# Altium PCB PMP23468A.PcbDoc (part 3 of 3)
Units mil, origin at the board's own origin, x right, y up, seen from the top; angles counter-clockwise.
Board outline 5250 x 3500 mil, 6 copper layers (Top Layer, Signal Layer 1, Signal Layer 2, Signal Layer 3, Signal Layer 4, Bottom Layer), stack 61.8 mil thick; 157 components, 73 nets, 403 pads, 842 vias.
Unrouted connection lines stored in the file: 3.
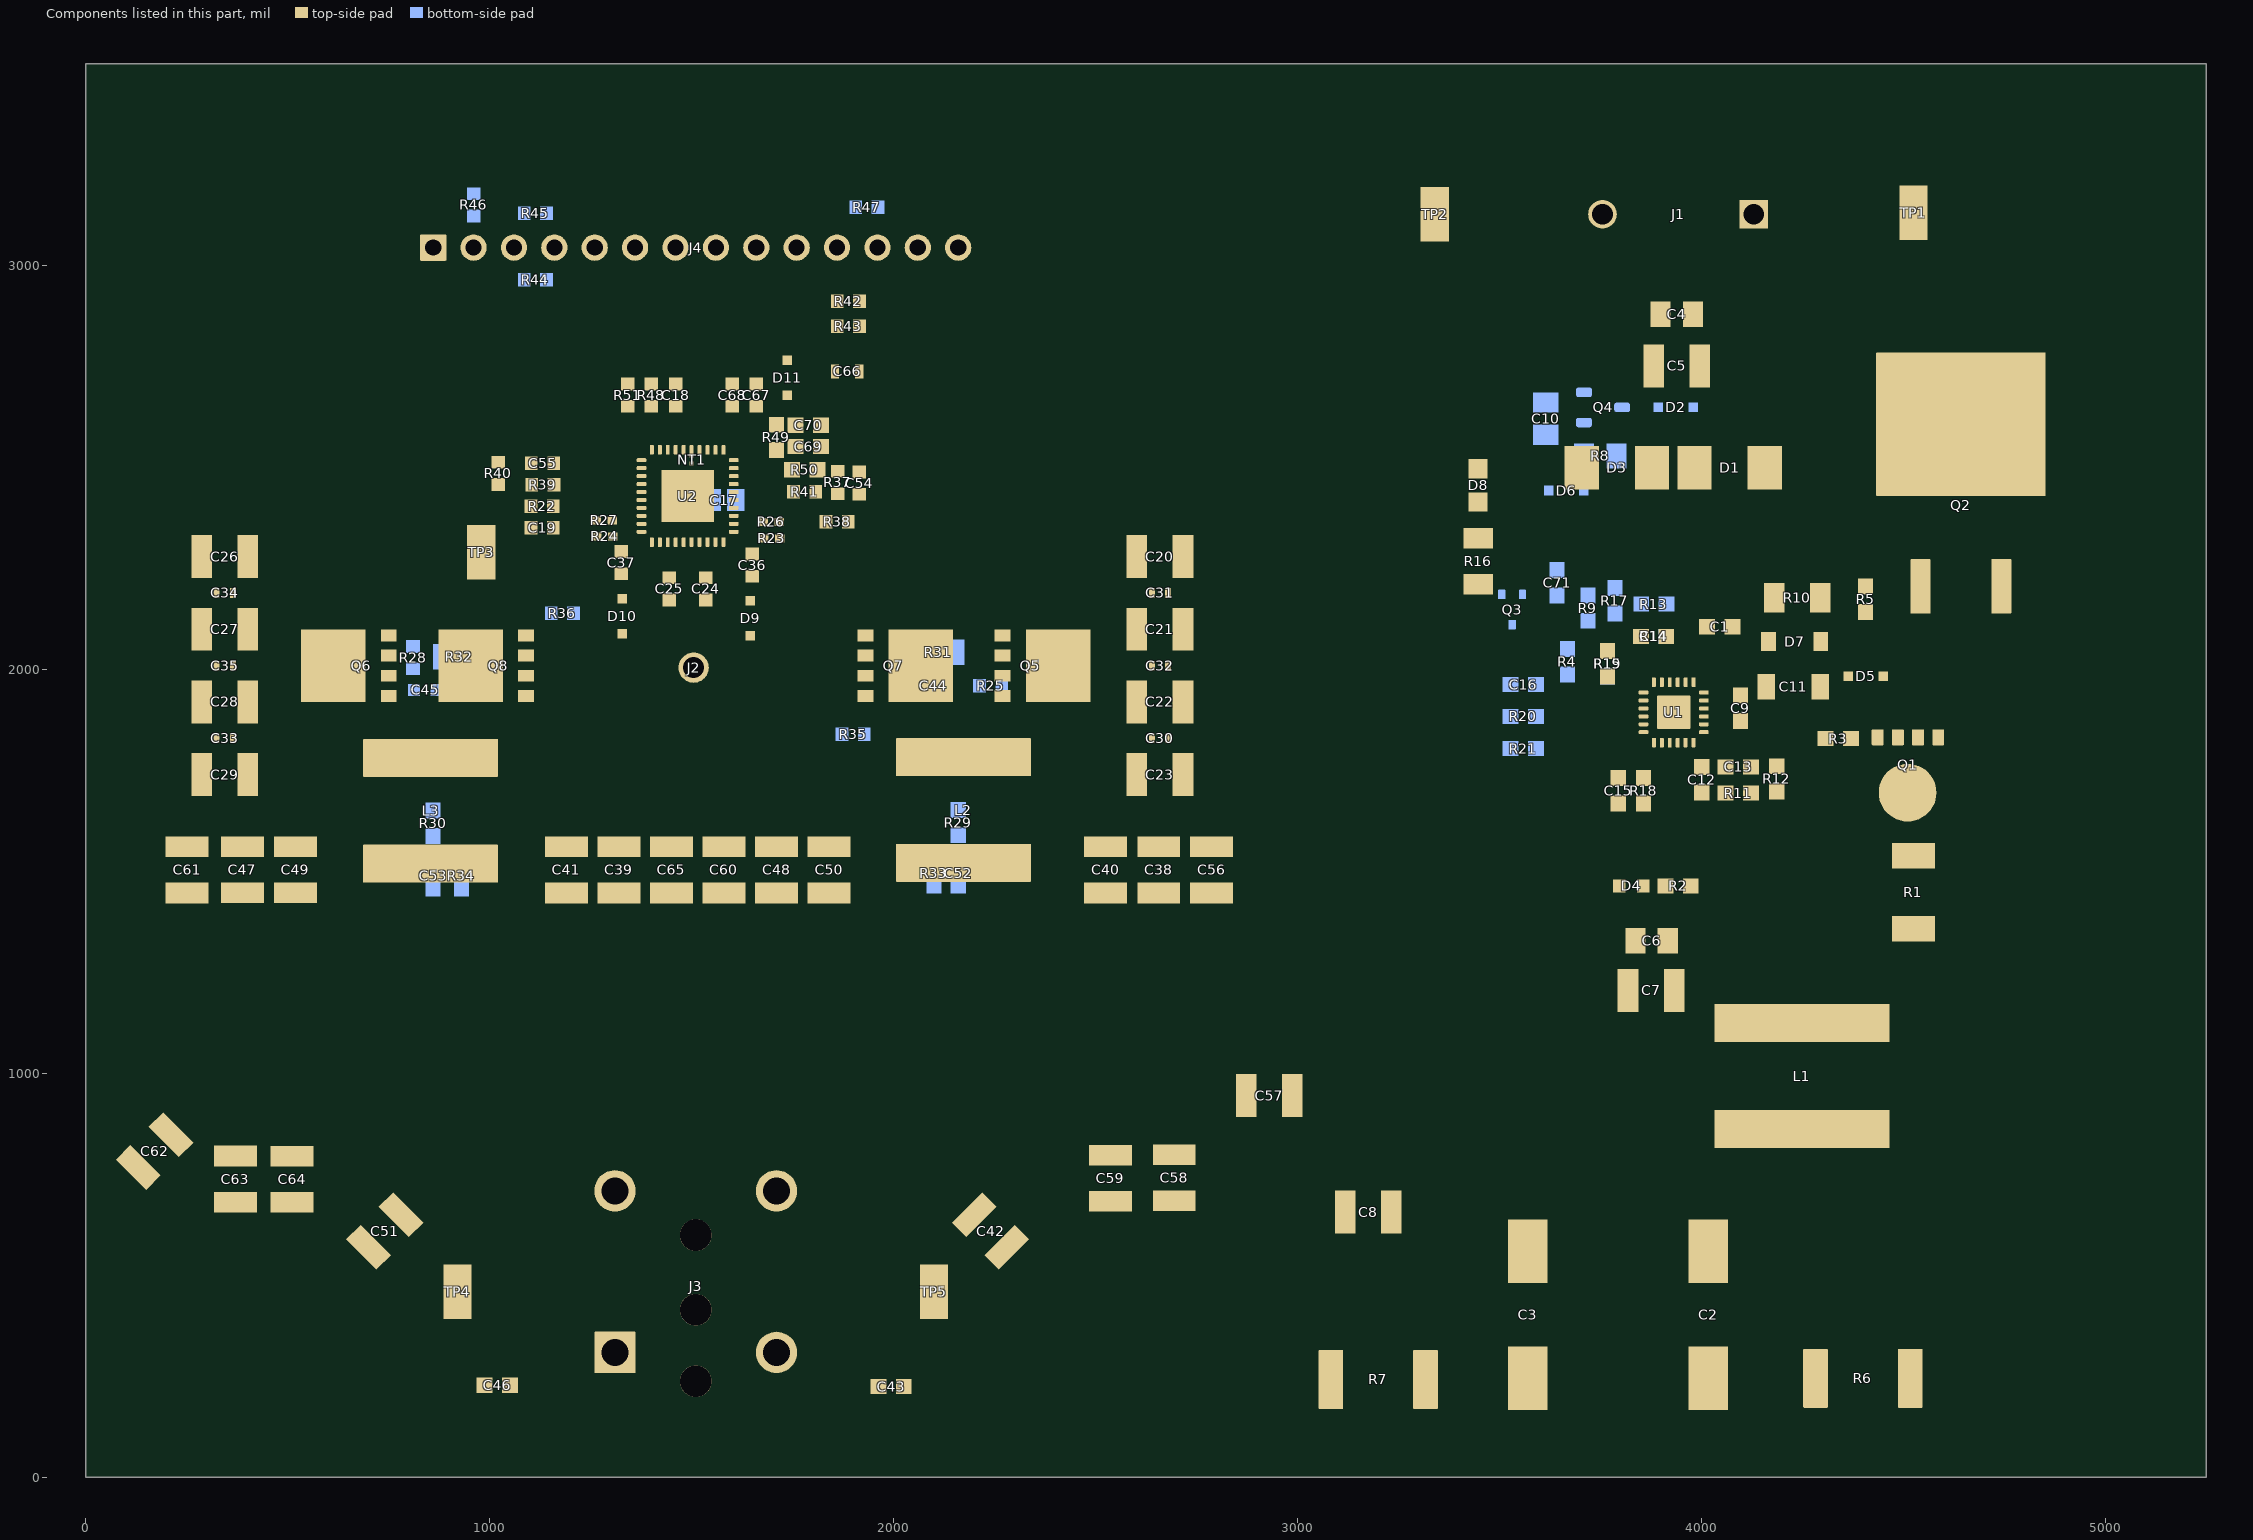
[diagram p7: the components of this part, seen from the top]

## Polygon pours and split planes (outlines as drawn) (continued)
VOUT on Top Layer "TOP_LAYER_VOUT_P1375" (solid, remove dead copper, pour order 1375): 2040,412.39 2040,524.11 2066.5,550.41 2177.18,549.57 2211.19,583.58 2396.22,768.61 2802.01,768.61 2900,866.59 2900,1436.67 2864.42,1472.25 2396.22,1472.25 2396.22,1568.47 2279.82,1684.86 2053.56,1684.86 1950.19,1581.49 1950.19,1472.25 1067.9,1472.25 1067.9,1564.65 993.7,1656.36 965.2,1684.86 754.73,1684.86 654.29,1564.65 654.29,1472.25 181.34,1472.25 141.72,1432.63 141.72,877.1 250.22,768.61 591.97,768.61 870,490.58 870,390 880,380 980.58,380 1028.52,332.06 1028.52,28.2 1983.58,28.2 1983.58,355.97
PGND on Top Layer "TOP_LAYER_PGND_P1417" (solid, pour order 1417): 0,3500 5250,3500 5250,0 0,0
VIN on Top Layer "TOP_LAYER_VIN_P1413" (solid, remove dead copper, pour order 1413): 349.58,1654.48 349.58,2358.44 728.37,2358.44 814.04,2272.77 814.04,2160.76 783.93,2130.65 670,2130.65 670,1696.32 628.16,1654.48
VBATT on Top Layer "TOP_LAYER_VBATT_P1384" (solid, remove dead copper, pour order 1384): 4900.01,2334.32 4344.71,2334.32 4237.02,2226.63 4237.02,2151.63 4220.71,2135.32 4156.71,2135.32 3947.75,2344.27 3947.75,3356.04 4029.7,3437.98 4961.71,3437.98 4961.71,2396.02
NetC37_1 on Top Layer "TOP_LAYER_NETC37_1_P1373" (solid, remove dead copper, pour order 1373): 670,2055.24 801.93,2055.24 831.32,2084.62 831.32,2112.36 1039,2112.36 1039,1727.87 670,1727.87
AGND on Top Layer "TOP_LAYER_AGND_P1374" (solid, remove dead copper, pour order 1374): 1800,2475.53 1920,2475.53 1920,2695.53 1770,2845.53 1311.51,2845.53 1185.07,2719.09 1185.07,2460 1290,2460 1290,2667.35 1318.18,2695.53 1710,2695.53 1800,2605.53
NetD1_2 on Top Layer "TOP_LAYER_NETD1_2_P1378" (solid, remove dead copper, pour order 1378): 4005.92,2599.72 3855.86,2599.84 3811.34,2555.35 3811.34,2451.03 3862.01,2400.36 4003.33,2400.36 4051.65,2448.68 4051.65,2553.96
VIN on Top Layer "TOP_LAYER_VIN_P1382" (solid, remove dead copper, pour order 1382): 3712.14,979.9 3591.09,1100.96 3310.96,1100.96 3190.63,980.63 3190.63,575.65 3325.33,440.96 3595.58,440.96 4904.7,440.96 4958.36,494.62 4958.36,932.52 4910.98,979.9
PGND on Top Layer "TOP_LAYER_PGND_P1383" (solid, remove dead copper, pour order 1383): 3753.28,1612.71 3822.5,1543.48 3822.5,1422.52 3823.03,1422.52 3871.7,1373.84 3871.7,1042.5 3822.88,993.67 3721.33,993.67 3599.39,1115.62 3295.6,1115.62 3077.75,1333.47 3077.75,3323.79 3191.94,3437.98 3848.36,3437.98 3930.65,3355.7 3930.65,2306.4 3959.19,2306.4 4129.87,2135.72 4129.87,2122.72 4140.37,2112.22 4167.37,2112.22 4183.37,2096.22 4183.37,2044.22 4177.37,2038.22 4123.48,2038.22 4081.48,2080.22 4055.37,2080.22 4052.37,2083.22 4052.37,2115.81 3991.36,2176.82 3863.97,2176.82 3739.87,2176.82 3703.67,2140.62 3703.67,1961.12 3726.23,1938.56 3726.23,1859.62 3771.03,1814.81 3817.76,1814.81 3826.69,1823.74 3871.7,1823.74 3877.19,1829.23 3883.11,1829.23 3886.92,1825.41 3886.92,1807.51 3878.44,1799.03 3851.01,1799.03 3820.37,1768.39 3820.37,1713.32 3813.77,1706.72 3763.19,1706.72 3753.28,1696.81
NetC6_1 on Top Layer "TOP_LAYER_NETC6_1_P1385" (solid, remove dead copper, pour order 1385): 3948.71,1422.52 3887.93,1361.74 3887.93,1077.9 3954.87,1010.96 4906.79,1010.96 4966.84,1071.01 4966.84,1364.6 4902.56,1428.88 4445.71,1428.88 4345.27,1529.32 3980.17,1529.32 3948.71,1497.85
PGND on Top Layer "TOP_LAYER_PGND_P1387" (solid, remove dead copper, pour order 1387): 3756.36,2821.38 3728.14,2793.15 3571.88,2793.15 3547.75,2817.28 3547.75,2956.19 3569.11,2977.55 3726.37,2977.55 3756.36,2947.56
NetQ1_5-6 on Top Layer "TOP_LAYER_NETQ1_5-6_P1391" (solid, remove dead copper, pour order 1391): 4475.28,1468.25 4901.25,1468.25 4962.71,1529.7 4962.71,1710.42 4887.63,1785.5 4429.87,1785.5 4389.71,1745.33 4389.71,1553.83
VIN on Top Layer "TOP_LAYER_VIN_P1392" (solid, pour order 1392): 4234.61,2266.07 4234.61,2149.22 4220.71,2135.32 4161.71,2135.32 4070.75,2226.28 4070.75,2257.72 4115.54,2302.52 4198.16,2302.52
PGND on Top Layer "NONET_L-01_P-001" (solid, remove dead copper, pour order 1395): 4169.71,2114.32 4142.71,2114.32 4121.71,2135.32 4061.71,2135.32 4054.71,2128.32 4054.71,2085.32 4057.71,2082.32 4083.82,2082.32 4132.76,2033.38 4132.76,1930.65 4142.93,1920.49 4179.77,1920.49 4185.71,1926.42 4185.71,2098.32
A on Top Layer "NONET_L-01_P-001" (solid, remove dead copper, pour order 1396): 4962.71,2260.65 4962.71,1830.35 4925.48,1793.12 4483.9,1793.12 4471.71,1805.32 4471.71,1854.32 4422.71,1903.32 4422.71,2075.32 4470.71,2123.32 4581.29,2123.32 4601.71,2143.74 4601.71,2284.32 4618.71,2301.32 4797.71,2301.32 4922.04,2301.32
VIN on Top Layer "TOP_LAYER_VIN_P1399" (solid, remove dead copper, pour order 1399): 2656.53,1648 2656.53,2351.96 2295.56,2351.96 2209.88,2266.29 2209.88,2154.29 2240,2124.17 2316.67,2124.17 2316.67,1727.11 2395.77,1648
NetC3_2 on Top Layer "TOP_LAYER_NETC3_2_P1400" (solid, pour order 1400): 3286.31,340 3620,340 3651.62,308.38 3651.62,178.76 3618.07,145.21 3286.64,145.21 3250.8,181.05 3250.8,304.49
NetC2_2 on Top Layer "TOP_LAYER_NETC2_2_P1401" (solid, pour order 1401): 3958.42,340 4302.1,340 4337.91,304.18 4337.91,182 4301.13,145.21 3961.71,145.21 3930.8,176.13 3930.8,312.38
PGND on Signal Layer 2 "SIGNAL_LAYER_2_PGND_P1405" (solid, pour order 1405): 0,3500 5250,3500 5250,-10 5240,0 -10,0
VIN on Signal Layer 2 "SIGNAL_LAYER_2_VIN_P1394" (solid, remove dead copper, pour order 1394): 707.26,2130.65 783.93,2130.65 814.04,2160.76 814.04,2272.77 812.96,2272.77 727.29,2358.44 406.37,2358.44 406.37,1528.2 559.28,1375.29 2599.52,1369.48 3190.63,778.37 3190.63,576.42 3326.09,440.96 3490.66,440.96 3591.09,541.39 3591.09,1038.45 3528.58,1100.96 3283.09,1100.96 2810,1574.04 2684.04,1700 2646.88,1700 2617.56,1729.32 2617.56,2351.96 2295.56,2351.96 2209.89,2266.29 2209.88,2154.29 2240,2124.17 2302.39,2124.17 2302.65,2124.44 2302.65,1757.56 2279.46,1733.9 1632.39,1733.9 1588.69,1777.6 1588.69,2258.59 1664.01,2333.9 1664.01,2435.69 1657.42,2442.28 1622.91,2442.28 1617.78,2437.14 1617.78,2377.02 1555.49,2314.73 1452.32,2314.73 1429.01,2291.42 1429.01,1773.9 1364.06,1708.95 748.96,1708.95 707.26,1750.65
VBATT on Signal Layer 2 "SIGNAL_LAYER_2_VBATT_P1402" (solid, remove dead copper, pour order 1402): 3987.71,3313.64 3987.71,2414.32 3935.71,2362.32 3935.71,2254.32 3895.71,2214.32 3895.71,2121.32 3904.71,2112.32 3953.71,2112.32 3964.71,2123.32 3964.71,2171.32 3949.71,2186.32 3949.71,2221.32 4029.71,2301.32 4177.71,2301.32 4306.71,2430.32 4875.43,2430.32 4961.71,2516.6 4961.71,3335.87 4828.04,3469.54 4143.61,3469.54
PGND on Bottom Layer "BOTTOM_LAYER_PGND_P1409" (solid, pour order 1409): 0,3500 5250,3500 5250,0 0,0
VIN on Bottom Layer "BOTTOM_LAYER_VIN_P1377" (solid, remove dead copper, pour order 1377): 439.28,1888.78 374.01,1888.78 374.01,1648 695.2,1648 707.26,1660.07 707.26,1985 814.04,1985 814.04,2133.11 814.04,2271.69 728.16,2357.57 374.01,2357.57 374.01,2078.73 439.28,2078.73
NetQ1_5-6 on Bottom Layer "BOTTOM_LAYER_NETQ1_5-6_P1412" (solid, remove dead copper, pour order 1412): 4475.28,1468.25 4901.25,1468.25 4962.71,1529.7 4962.71,1710.42 4887.63,1785.5 4429.87,1785.5 4389.71,1745.33 4389.71,1553.83
PGND on Bottom Layer "BOTTOM_LAYER_PGND_P1389" (solid, remove dead copper, pour order 1389): 3548.71,2789.22 3548.71,2627.81 3569.8,2606.72 3647.31,2606.72 3657.71,2596.32 3657.71,2446.32 3727.71,2376.32 3873.01,2376.32 3975.86,2273.47 4102.56,2273.47 4151.71,2224.32 4151.71,2062.32 4140.71,2051.32 4099.71,2051.32 4056.26,2094.77 3960.8,2094.92 3941.55,2075.67 3941.55,1990.27 3879.54,1928.26 3879.54,1809 3911.61,1776.94 3909.01,1656.32 3624.71,1372.02 3624.71,1200.32 3567.22,1142.83 3196.2,1142.83 3175.11,1163.92 3175.11,1410.73 3175.11,2793.32 3267.41,2885.62 3452.31,2885.62
VBATT on Bottom Layer "BOTTOM_LAYER_VBATT_P1379" (solid, remove dead copper, pour order 1379): 3894.56,2180.93 3901.1,2187.47 3965.29,2187.47 3967.94,2184.82 3967.94,2136.55 3966.66,2135.27 3903.08,2135.27 3894.58,2143.77
NetC6_1 on Bottom Layer "BOTTOM_LAYER_NETC6_1_P1380" (solid, remove dead copper, pour order 1380): 3954.87,1010.96 3888.26,1077.57 3888.26,1361.41 3887.93,1361.74 3948.71,1422.52 3948.71,1497.85 3980.17,1529.32 4345.27,1529.32 4445.71,1428.88 4902.56,1428.88 4966.84,1364.6 4966.84,1071.01 4906.79,1010.96 4885.59,1010.96
VBATT on Bottom Layer "BOTTOM_LAYER_VBATT_P1403" (solid, remove dead copper, pour order 1403): 4304.34,2285.87 4962.71,2285.87 4962.71,3437.98 4029.7,3437.98 3947.66,3355.95 3947.66,2293.06 3984.85,2255.87 4080.85,2255.87 4274.34,2255.87
VIN on Bottom Layer "BOTTOM_LAYER_VIN_P1386" (solid, remove dead copper, pour order 1386): 3750.43,440.96 3325.33,440.96 3190.63,575.65 3190.63,980.63 3310.96,1100.96 3591.09,1100.96 3712.14,979.9 4910.98,979.9 4958.36,932.52 4958.36,494.62 4904.7,440.96 4341.59,440.96
PGND on Bottom Layer "BOTTOM_LAYER_PGND_P1388" (solid, remove dead copper, pour order 1388): 3458.11,1740.62 3541.31,1740.62 3551.71,1751.02 3551.71,2017.42 3543.41,2025.72 3452.15,2025.72 3431.81,2005.38 3431.81,1766.91
A on Bottom Layer "NONET_L-01_P-001" (solid, remove dead copper, pour order 1398): 4474.4,2302.32 4961.71,2302.32 4961.71,1804.32 4472.33,1804.32 4422.71,1853.94 4422.71,2250.63
VIN on Bottom Layer "BOTTOM_LAYER_VIN_P1376" (solid, remove dead copper, pour order 1376): 2209.89,2266.29 2295.56,2351.96 2649.92,2351.96 2649.92,2097.01 2584.65,2097.01 2584.65,1894.25 2649.92,1894.25 2649.92,1648 2328.73,1648 2316.67,1660.07 2316.67,2003.21 2233.58,2003.21 2209.89,2026.9
PGND on Signal Layer 1 "SIGNAL_LAYER_1_PGND_P1404" (solid, pour order 1404): 0,3500 5250,3500 5250,0 0,0
PGND on Signal Layer 1 "SIGNAL_LAYER_1_PGND_P1397" (solid, remove dead copper, pour order 1397): 3077.75,1321.16 3283.29,1115.62 3599.39,1115.62 3721.33,993.67 3822.88,993.67 3871.7,1042.5 3871.7,1367.06 3820.8,1417.96 3820.8,1934.76 3932,2045.96 3932,3339.39 3833.41,3437.98 3181.46,3437.98 3077.75,3334.27
NetC6_1 on Signal Layer 1 "SIGNAL_LAYER_1_NETC6_1_P1411" (solid, remove dead copper, pour order 1411): 3948.71,1422.52 3887.93,1361.74 3887.93,1077.9 3954.87,1010.96 4906.79,1010.96 4966.84,1071.01 4966.84,1364.6 4902.56,1428.88 4445.71,1428.88 4345.27,1529.32 3980.17,1529.32 3948.71,1497.85
VIN on Signal Layer 1 "SIGNAL_LAYER_1_VIN_P1410" (solid, remove dead copper, pour order 1410): 3712.14,979.9 3591.09,1100.96 3310.96,1100.96 3190.63,980.63 3190.63,575.65 3325.33,440.96 3595.58,440.96 4904.7,440.96 4958.36,494.62 4958.36,932.52 4910.98,979.9
VBATT on Signal Layer 1 "SIGNAL_LAYER_1_VBATT_P1381" (solid, remove dead copper, pour order 1381): 4310.63,2291.99 4926.77,2291.99 4962.71,2327.93 4962.71,3284.97 4806.47,3441.21 4103.21,3441.21 3932.2,3270.19 3932.2,2320.93 3991.14,2261.99 4087.14,2261.99 4280.63,2261.99
A on Signal Layer 1 "SIGNAL_LAYER_1_A_P1393" (solid, pour order 1393): 4024.2,2302.32 4895.64,2302.32 4962.71,2235.25 4962.71,1804.47 4401.23,1804.47 4161.23,2044.47 3975.23,2044.47 3933.23,2002.47 3932.21,2001.45 3888.26,2001.45 3877.23,2012.47 3877.23,2155.35
NetQ1_5-6 on Signal Layer 1 "SIGNAL_LAYER_1_NETQ1_5-6_P1390" (solid, remove dead copper, pour order 1390): 4559.84,1785.5 4887.63,1785.5 4962.71,1710.42 4962.71,1529.7 4901.25,1468.25 4473.51,1468.25 3966.16,1975.6 3966.16,2043.21 4302.13,2043.21
PGND on Signal Layer 3 "SIGNAL_LAYER_3_PGND_P1416" (solid, pour order 1416): 0,3500 5250,3500 5250,-10 0,-10 -10,0
VIN on Signal Layer 3 "SIGNAL_LAYER_3_VIN_P1406" (solid, pour order 1406): 3591.09,1100.96 3712.14,979.9 4910.98,979.9 4958.36,932.52 4958.36,494.62 4904.7,440.96 4904.69,440.96 3326.09,440.96 3191.4,575.65 3190.63,575.65 3190.63,778.14 2599.52,1369.26 2599.52,1369.48 565.09,1369.48 406.37,1528.2 406.37,2358.44 727.29,2358.44 814.04,2271.69 814.04,2160.76 783.93,2130.65 707.26,2130.65 707.26,1750.65 748.96,1708.95 1364.06,1708.95 1429.01,1773.9 1429.01,2291.42 1452.32,2314.73 1555.49,2314.73 1617.78,2377.02 1617.78,2437.14 1620.48,2439.84 1654.99,2439.84 1657.42,2442.28 1664.01,2435.69 1664.01,2333.9 1588.69,2258.59 1588.69,1777.6 1632.39,1733.9 2279.46,1733.9 2302.65,1757.09 2302.65,2124.44 2302.39,2124.17 2240,2124.17 2209.88,2154.29 2209.89,2154.29 2209.89,2266.29 2295.56,2351.96 2617.56,2351.96 2617.56,1729.32 2646.88,1700 2684.04,1700 3283.09,1100.96
VOUT on Signal Layer 4 "SIGNAL_LAYER_4_VOUT_P1407" (solid, remove dead copper, pour order 1407): 993.7,1546.45 993.7,1656.36 965.2,1684.86 754.73,1684.86 730.01,1660.14 730.01,1550.62 651.64,1472.25 181.34,1472.25 141.72,1432.63 141.72,877.1 250.22,768.61 591.97,768.61 1028.52,332.06 1028.52,28.2 1983.58,28.2 1983.58,355.97 2211.19,583.58 2396.22,768.61 2802.02,768.61 2900,866.59 2900,1436.67 2864.42,1472.25 2372.25,1472.25 2285.48,1559.01 2285.48,1663.59 2264.22,1684.86 2053.56,1684.86 2035,1666.3 2035,1557.05 1950.19,1472.25 1067.9,1472.25
PGND on Signal Layer 4 "SIGNAL_LAYER_4_PGND_P1415" (solid, pour order 1415): 0,3500 5250,3500 5250,0 5245,-5 -5,-5

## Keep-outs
Keep-Out Layer:
  the board outline again, w10
  text ".Layer_Name" at 111,-1094.49 h60

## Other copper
Top Layer:
  region net PGND: 3878.64,1831.33 3853.11,1831.33 3776.71,1754.92 3776.71,1715.28 3779.86,1712.13 3812.68,1712.13 3817.37,1716.81 3817.37,1749.64 3866.75,1799.03 3878.6,1799.03 3887.42,1807.85 3887.42,1829.36 3885.45,1831.33
  region net NetQ1_5-6: 4064.71,2030.72 4108.75,2030.72 4114.42,2025.05 4114.42,1976.03 4109.01,1970.53 4076.64,1970.53 4044.72,1938.61 3995.85,1938.61 3994.7,1939.76 3994.7,1960.71
  region net PGND: 3765.22,1708.51 3753.53,1696.82 3737.11,1696.82 3730.31,1703.62 3730.31,1755.4 3745.4,1770.49 3804.04,1770.49 3814.95,1759.58 3814.95,1714.31 3809.15,1708.51
  region net A: 3956.31,2082.82 3956.31,2112.95 3973.68,2130.32 4030.22,2130.32 4034.22,2126.32 4034.22,2087.63 4000.6,2054.02 4000.6,2024.11 3966.16,1989.66 3966.16,1958.46 3965,1957.31 3957.47,1957.31 3956.31,1958.46
  region net NetC9_1: 4219.77,1812.38 4376.71,1969.32 4376.71,2218.32 4362.54,2232.49 4286.05,2232.49 4266.1,2212.54 4266.1,1974.34 4185.84,1894.08 4122.57,1894.08 4075.74,1894.08 4060.74,1909.08 3995.85,1909.08 3994.7,1907.93 3994.7,1900.39 3995.85,1899.24 4030.17,1899.24 4117.03,1812.38
  text ".Layer_Name" at 111,-1094.49 h60
Signal Layer 1:
  text "'.Layer_Name'" at 109,-1096 h60
Signal Layer 2:
  text "'.Layer_Name'" at 109,-1096 h60
Signal Layer 3:
  text "'.Layer_Name'" at 114,-1096 h60
Signal Layer 4:
  text "'.Layer_Name'" at 109,-1096 h60
Bottom Layer:
  text ".Layer_Name" at 111,-1094.49 h60

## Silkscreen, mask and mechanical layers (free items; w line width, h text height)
Top Overlay:
  lines w5: 3790.77,2387.55 3799.27,2387.55 ; 3807.75,2406.81 3813.77,2400.8 3813.77,2387.8 ; 3819.78,2368.78 3813.77,2374.8 3813.77,2387.8 ; 3828.26,2387.8 3836.77,2387.8 ; 4382.71,1921.07 4391.21,1921.07 4405.71,1935.57 4405.71,1907.07 4391.71,1921.07 ; 4389.71,1908.07 4389.71,1921.07 4389.71,1934.07 ; 4405.71,1921.32 4414.21,1921.32 ; 4408.59,2058 4417.09,2058 ; 4427.08,2077.27 4433.09,2071.25 4433.09,2058.25 4433.09,2045.25 4439.11,2039.24 ; 4431.09,2058.25 4417.09,2072.25 4417.09,2043.76 4431.59,2058.25 4440.09,2058.25 ; 3813.77,2387.8 3799.27,2402.29 3799.27,2373.3 3813.77,2387.8 ; 3813.77,2387.8 3828.26,2373.3 3828.26,2402.29 3813.77,2387.8
  text "VIN:" at 3015.16,3343.98 h100
  text "48VDC" at 2973.76,3245.19 h85
  text "(65VDC Max)" at 2924.85,3177.99 h65
  text "PG2" at 1178.91,3130 h40 r90
  text "AGND" at 1581.81,3130 h40 r90
  text "EN2" at 978.7,3129.02 h40 r90
  text "VCC" at 1085.41,3129.02 h40 r90
  text "PG1" at 1676.78,3126.3 h40 r90
  text "PGND" at 880.53,3125 h40 r90
  text "EN1" at 1780.12,3124.88 h40 r90
  text "VDDA" at 1371.46,3124.12 h40 r90
  text "VPWM" at 1881.65,3124.12 h40 r90
  text "VIN" at 1980.98,3124.33 h40 r90
  text "A" at 2080,3124.12 h40 r90
  text "PGND" at 2180,3124.12 h40 r90
  text "SYNCOUT" at 1276.38,3119.17 h40 r90
  text "DEMB- / SYNCIN" at 1560,3025 h40 r90
  text "-" at 3432.26,2886.73 h200
  text "+" at 4385.21,2863.98 h200
  text "GND" at 3293.99,2862.7 h35
  text "PMP23468 REV A" at 2408.1,2767.28 h60
  text "GND" at 1596.88,1886.94 h40
  text "CAUTION: / HOT SURFACE" at 1230.02,1521.91 h40
  text "VIN" at 4756.6,900 h45
  text "VOUT = 5VDC @ 50A MAX" at 1141.61,847 h40
  text "PGND" at 2620,394.56 h65
  text "VOUT+" at 670,380 h40
  text "VOUT-" at 2170,380 h40
  text "-" at 2021.58,97.27 h200
  text "+" at 952.16,80 h200
  text ".Layer_Name" at 111,-1094.49 h60
Bottom Overlay:
  lines w5: 3589.74,2379.32 3598.24,2379.32 ; 3606.72,2398.59 3612.74,2392.57 3612.74,2379.57 ; 3618.75,2360.56 3612.74,2366.57 3612.74,2379.57 ; 3621.24,2379.57 3612.74,2379.57 ; 3612.74,2379.57 3598.24,2394.07 3598.24,2365.08 3612.74,2379.57
  text ".Layer_Name" at 111,-1094.49 h60
Top Paste:
  text ".Layer_Name" at 111,-1094.49 h60
Bottom Paste:
  text ".Layer_Name" at 111,-1094.49 h60
Top Solder:
  text ".Layer_Name" at 111,-1094.49 h60
  text ".Layer_Name" at 111,-1094.49 h60
Bottom Solder:
  text ".Layer_Name" at 111,-1094.49 h60
Drill Guide:
  text ".Layer_Name" at 111,-1094.49 h60
M1 Board Outline:
  the board outline again, w10
  text ".Layer_Name" at 111,-1094.49 h60
M2 Board Dimensions:
  rectangle: -466,-511 -341,-386
  rectangle: -341,-636 34,-511
  lines w7: -466,-511 534,-511 ; -341,-636 -341,-386 ; -216,-636 -216,-386 ; 34,-636 34,-386 ; 284,-636 284,-386 ; -466,-636 534,-636 534,-386 -466,-386 -466,-636
  text ".Layer_Name" at 111,-1094.49 h60
M3 3D STEP Top:
  text ".Layer_Name" at 111,-1094.49 h60
M4 3D STEP Bottom:
  text ".Layer_Name" at 111,-1094.49 h60
M5 Assembly Top:
  circle w3.94: c867.95,900.24 r8.8
  lines w10: -758,-1166.17 5842,-1166.17 ; -758,-962.83 5844,-962.83 ; -758,-759.5 -758,-1369.5 3247,-1369.5 5844,-1369.5 5844,-759.5 -757.5,-759.5 -757.5,-1369.5 818,-1369.5 ; 1707,-1369.5 1707,-759.5 ; 2974,-962.83 2974,-759.5 ; 3814,-962.83 3814,-759.5 ; 4436,-1376 4436,-1173.17
  text "COMPONENTS MARKED 'DNP' SHOULD NOT BE POPULATED." at 687.5,-554.5 h60
  text "ASSEMBLY VARIANT:" at 687,-670 h60
  text ".VariantName" at 1723,-670 h60
  text "PCB VIEWED FROM TOP SIDE" at -694.5,-891.67 h60
  text "BOARD #:" at 1782,-891.67 h60
  text ".PRJ_Number" at 2327.5,-891.67 h60
  text "REV:" at 3172,-891.67 h60
  text ".PCB_Rev" at 3463.5,-891.67 h60
  text "SVN REV:" at 4010,-891.67 h60
  text ".VersionControl_RevNumber" at 4516,-891.67 h60
  text "TID #:" at 1782,-1095 h60
  text ".TID" at 2327.5,-1095 h60
  text "PLOT NAME =" at -694.5,-1300.34 h60
  text ".plot_File_Name" at 111,-1300.34 h60
  text "GENERATED    :" at 1784,-1300.34 h60
  text ".Print_Date" at 2653.5,-1300.34 h60
  text ".Print_Time" at 3382.5,-1300.34 h60
  text "TEXAS INSTRUMENTS" at 4647,-1300.34 h60
M6 Assembly Bottom:
  lines w10: -758.5,-963.33 5843.5,-963.33 ; -756.5,-1166.67 5843.5,-1166.67 ; 649.5,-1376.5 649.5,-1173.67 ; 1271.5,-963.33 1271.5,-760 ; 2111.5,-963.33 2111.5,-760 ; 3378.5,-1370 3378.5,-760 ; 4267.5,-1370 5843,-1370 5843,-760 -758.5,-760 -758.5,-1370 1838.5,-1370 5843.5,-1370 5843.5,-760
  text "COMPONENTS MARKED 'DNP' SHOULD NOT BE POPULATED." at 5636,-554 h60
  text ".VariantName" at 4592,-670 h60
  text "ASSEMBLY VARIANT:" at 5631,-670 h60
  text ".VersionControl_RevNumber" at 569.5,-892.17 h60
  text "SVN REV:" at 1075.5,-892.17 h60
  text ".PCB_Rev" at 1622,-892.17 h60
  text "REV:" at 1913.5,-892.17 h60
  text ".PRJ_Number" at 2758,-892.17 h60
  text "BOARD #:" at 3303.5,-892.17 h60
  text "PCB VIEWED FROM BOTTOM SIDE" at 5780,-892.17 h60
  text ".TID" at 2758,-1095.5 h60
  text "TID #:" at 3303.5,-1095.5 h60
  text "TEXAS INSTRUMENTS" at 438.5,-1300.84 h60
  text ".Print_Time" at 1703,-1300.84 h60
  text ".Print_Date" at 2432,-1300.84 h60
  text "GENERATED    :" at 3301.5,-1300.84 h60
  text ".plot_File_Name" at 4974.5,-1300.84 h60
  text "PLOT NAME =" at 5780,-1300.84 h60
M9 Title Sheet:
  drawing of 57 lines, arcs and shapes, not listed
  text "1" at 273.84,7800.5 h70
  text "2" at 2769.5,7800.5 h70
  text "3" at 5258.84,7800.5 h70
  text "4" at 7765.51,7800.5 h70
  text "5" at 10264.5,7800.5 h70
  text "6" at 12769.5,7800.5 h70
  text "A" at -882.5,6657.5 h70
  text "A" at 13917.5,6657.5 h70
  text "B" at -882.5,4277.5 h70
  text "B" at 13917.5,4277.5 h70
  text "C" at -882.5,1902.5 h70
  text "C" at 13917.5,1902.5 h70
  text "PROJECT TITLE:" at 10877.5,41.5 h45
  text ".PRJ_Title" at 10927.5,-91.83 h70
  text "DESIGNED FOR:" at 10877.5,-259.5 h45
  text ".PRJ_Customer" at 10927.5,-399.5 h70
  text "D" at -882.5,-467.5 h70
  text "D" at 13917.5,-467.5 h70
  text "FILE NAME:" at 10877.5,-559.5 h45
  text ".PCB_File_Name_No_Path" at 10927.5,-679.5 h70
  text "Texas Instruments (TI) and/or its licensors do not warrant the accuracy or completeness of this specification" at 5908,-841.34 h45
  text "ENGINEER:" at 10877.5,-849.5 h45
  text "LAYOUT BY:" at 12382.5,-849.5 h45
  text "or any information contained therein. TI and/or its licensors do not warrant that this design will meet" at 5863.01,-954 h45
  text ".PRJ_Engineer" at 10927.5,-1004.49 h70
  text ".PCB_Layout" at 12433,-1004.49 h70
  text "the specifications, will be suitable for your application or fit for any particular purpose, or will operate in" at 5863.01,-1066.67 h45
  text ".Layer_Name" at 111,-1094.49 h60
  text "ALTIUM DESIGNER VERSION:" at 12382.5,-1159.5 h45
  text "an implementation. TI and/or its licensors do not warrant that the design is production worthy. You should" at 5863.01,-1179.33 h45
  text "completely validate and test your design implementation to confirm the system functionality for your application." at 5908,-1292 h45
  text ".print_Scale" at 10927.5,-1292.83 h70
  text ".Application_BuildNumber" at 12433,-1292.83 h70
  text "1" at 273.84,-1499.5 h70
  text "2" at 2769.5,-1499.5 h70
  text "3" at 5258.84,-1499.5 h70
  text "4" at 7765.51,-1499.5 h70
  text "5" at 10264.5,-1499.5 h70
  text "6" at 12769.5,-1499.5 h70
M10 Fab Notes:
  drawing of 189 lines, arcs and shapes, not listed
  text "DESIGN INFORMATION" at 11916.02,6120.17 h60
  text "MIN. TRACK WIDTH:" at 11271.46,5988.05 h60
  text "7" at 12367.7,5988.05 h60
  text "MIL" at 12522.46,5988.05 h60
  text "MIN. CLEARANCE:" at 11271.46,5863.92 h60
  text "0.2" at 12307.7,5863.93 h60
  text "mm" at 12522.46,5863.92 h60
  text "MIN. VIA PAD SIZE:" at 11271.46,5739.8 h60
  text "19.685" at 12130,5739.8 h60
  text "MIL" at 12522.46,5739.8 h60
  text "0.05mm (2MIL)" at 11966.46,5609.9 h60
  text "MINIMUM ANNULAR RING" at 10942.23,5601.67 h60
  text "EXTERNAL" at 12674.46,5601.67 h60
  text "PER" at 11142.23,5491.55 h60
  text "IPC-D-275 CLASS 2 LEVEL C" at 11362.23,5491.54 h60
  text "MIL, HOLES" at 12850.46,5391.07 h60
  text "+/-" at 12458,5382.48 h60
  text "+/-" at 13312,5382.48 h60
  text "REGISTRATION TOLERANCES:" at 10942.23,5381.42 h60
  text "METAL" at 12142,5381.42 h60
  text "5" at 12718.2,5381.42 h60
  text "3" at 13551.2,5381.42 h60
  text "MIL" at 13667.46,5381.42 h60
  text "HOLE SIZE TOLERANCE (UNLESS OTHERWISE SPECIFIED):" at 10942.23,5283.1 h60
  text "+/-" at 13312,5280.23 h60
  text "3" at 13551.2,5279.17 h60
  text "MIL" at 13667.46,5279.17 h60
  text "MATERIAL:" at 10867.46,5141.52 h60
  text "FR-4 High Tg" at 11853.9,5013 h60
  text "X" at 11709.46,5005.01 h60
  text "FR-408" at 11288.46,5000.49 h60
  text "OTHER" at 12776.46,5000.49 h60
  text "62 MIL (1.6mm) +/-10%" at 11608.56,4857.46 h60
  text "X" at 11488.46,4855.01 h60
  text "THICKNESS:" at 10942.23,4849.24 h60
  text "OTHER" at 12893.46,4849.24 h60
  text "TOLERANCE:" at 10942.23,4710.92 h60
  text "X" at 11790.46,4710.92 h60
  text "ANSI IPC-6012 TYPE 3 CLASS 2" at 11968.48,4710.92 h60
  text "OTHER +/-" at 11968.46,4566.73 h60
  text "BOW & TWIST:" at 10942.23,4421.54 h60
  text "X" at 11790.46,4421.54 h60
  text "ANSI IPC-6012 TYPE 3 CLASS 2" at 11968.48,4421.54 h60
  text "OTHER +/-" at 11968.46,4274.85 h60
  text "DRILLING:" at 10867.46,4144.23 h60
  text "NC_DRILL FILES" at 12628.46,4039.04 h60
  text "REFERENCE:" at 10942.23,4035.1 h60
  text "X" at 11599.46,4035.01 h60
  text "AS SHOWN" at 11777.46,4035.1 h60
  text "X" at 12500.46,4035.1 h60
  text "OTHER" at 12926.46,3892.85 h60
  text "PTH COPPER THICKNESS:" at 10941.91,3889.32 h60
  text "X" at 12081.14,3889.32 h60
  text "20-30 um" at 12209.14,3889.32 h60
  text "BOARD FINISH:" at 10867.46,3741.73 h60
  text "SILKSCREEN:" at 11022.68,3631.6 h60
  text "X" at 11980.46,3631.6 h60
  text "TOP" at 12097.46,3631.6 h60
  text "X" at 12490.46,3631.6 h60
  text "BOTTOM" at 12608.46,3631.6 h60
  text "SILKSCREEN COLOR:" at 11022.68,3476.41 h60
  text "X" at 11979.46,3476.41 h60
  text "WHITE" at 12097.46,3476.41 h60
  text "OTHER" at 12608.46,3476.41 h60
  text "X" at 12110.46,3332.96 h60
  text "GREEN" at 12228.46,3332.96 h60
  text "OTHER" at 12846.46,3332.96 h60
  text "SOLDER RESIST COLOR:" at 11022.68,3326.1 h60
  text "X" at 12110.46,3178.71 h60
  text "MATTE" at 12228.46,3178.71 h60
  text "SEMI-GLOSS" at 12846,3178.07 h60
  text "IMMERSION GOLD (ENIG)" at 11928.46,3005.94 h60
  text "ENEPIG" at 13266,2998.72 h60
  text "SURFACE FINISH:" at 10867.46,2997.72 h60
  text "X" at 11750.46,2997.72 h60
  text "IMM. TIN/SILVER OR EQUIV" at 11197,2860.4 h60
  text "OTHER" at 12628.46,2856.47 h60
  text "ARRAY/PANEL:" at 10867.46,2701.09 h60
  text "CUT AND TRIM PER M1 BOARD OUTLINE" at 11928.46,2692.87 h60
  text "N.C. ROUTE" at 11928.46,2556.9 h60
  text "X" at 12616.46,2556.9 h60
  text "V. SCORE" at 12794.46,2556.9 h60
  text "CERTIFICATION:" at 10867.46,2427.77 h60
  text "MATERIALS AND WORKMANSHIP FOR ALL PCBS" at 11592.46,2427.77 h60
  text "TO MEET OR EXCEED THE REQUIREMENTS OF:" at 11592.46,2333.71 h60
  text "X" at 11229.97,2205.08 h60
  text "ANSI IPC-A-600F CLASS ->" at 11357.96,2205.08 h60
  text "X" at 13005.97,2205.08 h60
  text "2" at 13115.96,2205.08 h60
  text "1" at 12800.96,2203.58 h60
  text "3" at 13469.96,2203.58 h60
  text "X" at 12041.97,2057.39 h60
  text "RoHS" at 12169.96,2057.39 h60
  text "OTHER" at 12814.36,2057.39 h60
  text "PER ORDER" at 13211.42,2057.39 h60
  text "ALL BOARDS MUST MEET OR EXCEED UL94-V0 REQUIREMENTS." at 10895,1903.57 h60
  text "PCB MUST BEAR THE UL94V-0 UL REGISTERED MATERIAL ID NUMBER" at 10895,1787.5 h60
  text "ADDITIONAL REQUIREMENTS:" at 10867.46,1618.08 h60
  text "MICROSECTION:" at 10942.23,1510.95 h60
  text "YES" at 11847.96,1510.95 h60
  text "REQUIRED" at 12709.46,1366.62 h60
  text "BARE BOARD ELEC. TEST:" at 10942.23,1363.76 h60
  text "NONE" at 12247.96,1363.76 h60
  text "X" at 12591.46,1363.76 h60
  text "PER ORDER" at 13301.46,1363.76 h60
  text "XX MIL VIAS REQUIRE NON-CONDUCTIVE FILL AND PLANARIZE" at 11110.38,1158.82 h59
  text "XX MIL VIAS REQUIRE CONDUCTIVE FILL AND PLANARIZE" at 11118.38,1054.84 h60
  text "OUTER XX MIL TRACES REQUIRE 50 OHM SINGLE-ENDED IMPEDANCE" at 11117.39,891.46 h58
  text "LAYER 2 & 3 (INNER LAYERS) XX MIL WIDE, XX MIL SPACE / TRACES REQUIRE 100 OHM DIFFERENTIAL IMPEDANCE" at 11109.39,655.74 h60
  text ".Layer_Name" at 111,-1094.49 h60
M11 Gerber Information:
  lines w10: -758,-1166.17 5842,-1166.17 ; -758,-962.83 5844,-962.83 ; -758,-759.5 -758,-1369.5 3247,-1369.5 5844,-1369.5 5844,-759.5 -757.5,-759.5 -757.5,-1369.5 818,-1369.5 ; 1707,-1369.5 1707,-759.5 ; 2974,-962.83 2974,-759.5 ; 3814,-962.83 3814,-759.5 ; 4436,-1376 4436,-1173.17
  text "ALL ARTWORK VIEWED FROM TOP SIDE" at -694.5,-891.67 h60
  text "BOARD #:" at 1782,-891.67 h60
  text ".PRJ_Number" at 2327.5,-891.67 h60
  text "REV:" at 3172,-891.67 h60
  text ".PCB_Rev" at 3463.5,-891.67 h60
  text "SVN REV:" at 4010,-891.67 h60
  text ".VersionControl_RevNumber" at 4516,-891.67 h60
  text "LAYER NAME =" at -694.5,-1094.49 h60
  text "TID #:" at 1782,-1095 h60
  text ".TID" at 2327.5,-1095 h60
  text "PLOT NAME =" at -694.5,-1300.34 h60
  text ".plot_File_Name" at 111,-1300.34 h60
  text "GENERATED    :" at 1784,-1300.34 h60
  text ".Print_Date" at 2653.5,-1300.34 h60
  text ".Print_Time" at 3382.5,-1300.34 h60
  text "TEXAS INSTRUMENTS" at 4647,-1300.34 h60
M12 Stackup:
  drawing of 399 lines, arcs and shapes, not listed
  text "Layer" at 380.64,6300.01 h60
  text "Name" at 790.55,6300.01 h60
  text "Material" at 1730.29,6300.01 h60
  text "Thickness" at 2590.06,6300.01 h60
  text "Constant" at 3239.89,6300.01 h60
  text "Board Layer Stack" at 3809.75,6300.01 h60
  text "Top Overlay" at 790.55,6180.01 h60
  text "Top Solder" at 790.55,6060.01 h60
  text "Solder Resist" at 1730.29,6060.01 h60
  text "0.40mil" at 2590.06,6060.01 h60
  text "3.5" at 3239.89,6060.01 h60
  text "1" at 380.64,5940.01 h60
  text "Top Layer" at 790.55,5940.01 h60
  text "2.80mil" at 2590.06,5940.01 h60
  text "Dielectric1" at 790.55,5820.01 h60
  text "FR-4 High Tg" at 1730.29,5820.01 h60
  text "5.00mil" at 2590.06,5820.01 h60
  text "4.2" at 3239.89,5820.01 h60
  text "2" at 380.64,5700.01 h60
  text "Signal Layer 1" at 790.55,5700.01 h60
  text "2.80mil" at 2590.06,5700.01 h60
  text "Dielectric 2" at 790.55,5580.01 h60
  text "FR-4 High Tg" at 1730.29,5580.01 h60
  text "15.00mil" at 2590.06,5580.01 h60
  text "4.2" at 3239.89,5580.01 h60
  text "3" at 380.64,5460.01 h60
  text "Signal Layer 2" at 790.55,5460.01 h60
  text "2.80mil" at 2590.06,5460.01 h60
  text "Dielectric 3" at 790.55,5340.01 h60
  text "FR-4 High Tg" at 1730.29,5340.01 h60
  text "5.00mil" at 2590.06,5340.01 h60
  text "4.2" at 3239.89,5340.01 h60
  text "4" at 380.64,5220.01 h60
  text "Signal Layer 3" at 790.55,5220.01 h60
  text "2.80mil" at 2590.06,5220.01 h60
  text "Dielectric 4" at 790.55,5100.01 h60
  text "FR-4 High Tg" at 1730.29,5100.01 h60
  text "15.00mil" at 2590.06,5100.01 h60
  text "4.2" at 3239.89,5100.01 h60
  text "5" at 380.64,4980.01 h60
  text "Signal Layer 4" at 790.55,4980.01 h60
  text "2.80mil" at 2590.06,4980.01 h60
  text "Dielectric 5" at 790.55,4860.01 h60
  text "FR-4 High Tg" at 1730.29,4860.01 h60
  text "5.00mil" at 2590.06,4860.01 h60
  text "4.2" at 3239.89,4860.01 h60
  text "6" at 380.64,4740.01 h60
  text "Bottom Layer" at 790.55,4740.01 h60
  text "2.80mil" at 2590.06,4740.01 h60
  text "Bottom Solder" at 790.55,4620.01 h60
  text "Solder Resist" at 1730.29,4620.01 h60
  text "0.40mil" at 2590.06,4620.01 h60
  text "3.5" at 3239.89,4620.01 h60
  text "Bottom Overlay" at 790.55,4500.01 h60
  text ".Layer_Name" at 111,-1094.49 h60
M13 Component Bodies Top:
  text ".Layer_Name" at 111,-1094.49 h60
M14 Component Bodies Bottom:
  text ".Layer_Name" at 111,-1094.49 h60
M15 Courtyards Top:
  text ".Layer_Name" at 111,-1094.49 h60
M16 Courtyards Bottom:
  text ".Layer_Name" at 111,-1094.49 h60
Drill Drawing:
  circle w10: c6651.28,2051.95 r27.63
  lines w10: 6623.66,1278.4 6678.91,1278.4 6678.91,1333.65 6623.66,1333.65 6623.66,1278.4 ; 6623.66,1402.72 6678.91,1402.72 6678.91,1457.97 6623.66,1457.97 6623.66,1402.72 ; 6623.66,1582.29 6678.91,1582.29 6651.28,1527.04 6623.66,1582.29 ; 6623.66,1665.17 6637.47,1665.17 6651.28,1651.36 6665.1,1665.17 6678.91,1665.17 6665.1,1678.99 6678.91,1692.8 6665.1,1692.8 6651.28,1706.61 6637.47,1692.8 6623.66,1692.8 6637.47,1678.99 6623.66,1665.17 ; 6623.66,1775.68 6651.28,1789.49 6678.91,1775.68 6665.1,1803.31 6678.91,1830.93 6651.28,1817.12 6623.66,1830.93 6637.47,1803.31 6623.66,1775.68 ; 6623.66,1913.81 6637.47,1913.81 6637.47,1900 6665.1,1900 6665.1,1913.81 6678.91,1913.81 6678.91,1941.44 6665.1,1941.44 6665.1,1955.25 6637.47,1955.25 6637.47,1941.44 6623.66,1941.44 6623.66,1913.81 ; 6623.66,2148.64 6623.66,2162.45 6637.47,2176.27 6623.66,2190.08 6623.66,2203.89 6637.47,2203.89 6651.28,2190.08 6665.1,2203.89 6678.91,2203.89 6678.91,2190.08 6665.1,2176.27 6678.91,2162.45 6678.91,2148.64 6665.1,2148.64 6651.28,2162.45 6637.47,2148.64 6623.66,2148.64 ; 6623.66,2286.77 6637.47,2286.77 6637.47,2272.96 6665.1,2272.96 6665.1,2286.77 6678.91,2286.77 6678.91,2314.4 6665.1,2314.4 6665.1,2328.21 6637.47,2328.21 6637.47,2314.4 6623.66,2314.4 6623.66,2286.77 ; 6634.71,1289.45 6667.86,1289.45 6667.86,1322.6 6634.71,1322.6 6634.71,1289.45 ; 6634.71,1919.34 6643,1919.34 6643,1911.05 6659.57,1911.05 6659.57,1919.34 6667.86,1919.34 6667.86,1935.91 6659.57,1935.91 6659.57,1944.2 6643,1944.2 6643,1935.91 6634.71,1935.91 6634.71,1919.34
  lines w12: 6573.57,1241.1 9701.24,1241.1 ; 6573.57,2359.98 9701.24,2359.98 ; 6911.43,1116.78 6911.43,2484.3 ; 7212.91,1116.78 7212.91,2484.3 ; 7776.17,1116.78 7776.17,2484.3 ; 8035.32,1116.78 8035.32,2484.3 ; 8410.47,1116.78 8410.47,2484.3 ; 9134.8,1116.78 9134.8,2484.3 ; 6573.57,1116.78 9701.24,1116.78 9701.24,2484.3 6573.57,2484.3 6573.57,1116.78
  text "Symbol" at 6648.16,2397.28 h72
  text "Count" at 6948.73,2397.28 h72
  text "Hole Size" at 7250.2,2397.28 h72
  text "Plated" at 7813.47,2397.28 h72
  text "Hole Type" at 8072.61,2397.28 h72
  text "Drill Layer Pair" at 8447.77,2397.28 h72
  text "Hole Tolerance" at 9172.1,2397.28 h72
  text "17" at 6948.73,2272.96 h60
  text "7.87mil (0.200mm)" at 7250.2,2272.96 h60
  text "PTH" at 7813.47,2272.96 h60
  text "Round" at 8072.61,2272.96 h60
  text "Top Layer - Bottom Layer" at 8447.77,2272.96 h60
  text "2" at 6948.73,2148.64 h60
  text "8.00mil (0.203mm)" at 7250.2,2148.64 h60
  text "PTH" at 7813.47,2148.64 h60
  text "Round" at 8072.61,2148.64 h60
  text "Top Layer - Bottom Layer" at 8447.77,2148.64 h60
  text "567" at 6948.73,2024.32 h60
  text "10.00mil (0.254mm)" at 7250.2,2024.32 h60
  text "PTH" at 7813.47,2024.32 h60
  text "Round" at 8072.61,2024.32 h60
  text "Top Layer - Bottom Layer" at 8447.77,2024.32 h60
  text "256" at 6948.73,1900 h60
  text "12.00mil (0.305mm)" at 7250.2,1900 h60
  text "PTH" at 7813.47,1900 h60
  text "Round" at 8072.61,1900 h60
  text "Top Layer - Bottom Layer" at 8447.77,1900 h60
  text "14" at 6948.73,1775.68 h60
  text "40.00mil (1.016mm)" at 7250.2,1775.68 h60
  text "PTH" at 7813.47,1775.68 h60
  text "Round" at 8072.61,1775.68 h60
  text "Top Layer - Bottom Layer" at 8447.77,1775.68 h60
  text "2" at 6948.73,1651.36 h60
  text "51.18mil (1.300mm)" at 7250.2,1651.36 h60
  text "PTH" at 7813.47,1651.36 h60
  text "Round" at 8072.61,1651.36 h60
  text "Top Layer - Bottom Layer" at 8447.77,1651.36 h60
  text "1" at 6948.73,1527.04 h60
  text "52.00mil (1.321mm)" at 7250.2,1527.04 h60
  text "PTH" at 7813.47,1527.04 h60
  text "Round" at 8072.61,1527.04 h60
  text "Top Layer - Bottom Layer" at 8447.77,1527.04 h60
  text "4" at 6948.73,1402.72 h60
  text "66.93mil (1.700mm)" at 7250.2,1402.72 h60
  text "PTH" at 7813.47,1402.72 h60
  text "Round" at 8072.61,1402.72 h60
  text "Top Layer - Bottom Layer" at 8447.77,1402.72 h60
  text "3" at 6948.73,1278.4 h60
  text "78.74mil (2.000mm)" at 7250.2,1278.4 h60
  text "NPTH" at 7813.47,1278.4 h60
  text "Round" at 8072.61,1278.4 h60
  text "Top Layer - Bottom Layer" at 8447.77,1278.4 h60
  text "866 Total" at 6948.73,1154.08 h60
  text ".Layer_Name" at 111,-1094.49 h60
M17 Embedded Cavity:
  text ".Layer_Name" at 111,-1094.49 h60
M18 Embedded Assembly:
  text ".Layer_Name" at 111,-1094.49 h60
M19 Embedded Keepout:
  text ".Layer_Name" at 111,-1094.49 h60

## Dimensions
0,0 to 0,3500 on M2 Board Dimensions
0,0 to 5250,0 on M2 Board Dimensions
-466,-636 to 534,-636 on M2 Board Dimensions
